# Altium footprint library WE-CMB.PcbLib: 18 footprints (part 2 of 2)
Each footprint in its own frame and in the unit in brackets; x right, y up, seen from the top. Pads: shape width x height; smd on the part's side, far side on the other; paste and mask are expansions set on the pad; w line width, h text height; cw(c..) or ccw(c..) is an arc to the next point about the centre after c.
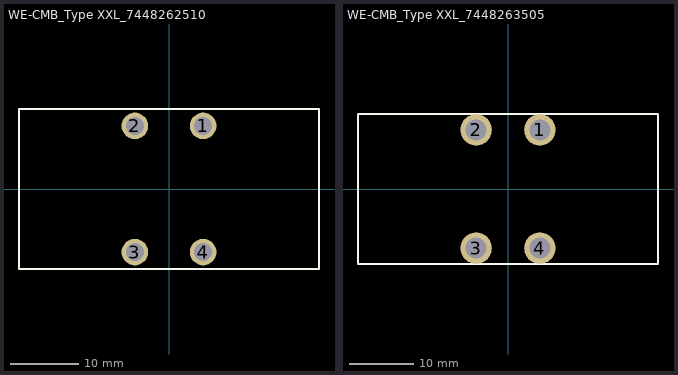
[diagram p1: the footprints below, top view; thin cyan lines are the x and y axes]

## WE-CMB_Type XXL_7448262510 [mm] "Common Mode Power Line Choke"
height 43
pads (4):
  round 3.9 hole 2.6: 1(5,9.25) 2(-5,9.25) 3(-5,-9.25) 4(5,-9.25)
Top Overlay:
  lines w0.3: -22,-11.75 -22,11.75 22,11.75 22,-11.75 -22,-11.75
3D body: height 39.95, standoff -4.75, extent -20.101,-11.5 20.1,11.5

## WE-CMB_Type XXL_7448263505 [mm] "Common Mode Power Line Choke"
height 43
pads (4):
  round 4.95 hole 3.3: 1(5,9.25) 2(-5,9.25) 3(-5,-9.25) 4(5,-9.25)
Top Overlay:
  lines w0.3: -23.5,-11.75 -23.5,11.75 23.5,11.75 23.5,-11.75 -23.5,-11.75
3D body: height 40.2, standoff -4.75, extent -20.35,-11.5 20.35,11.5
